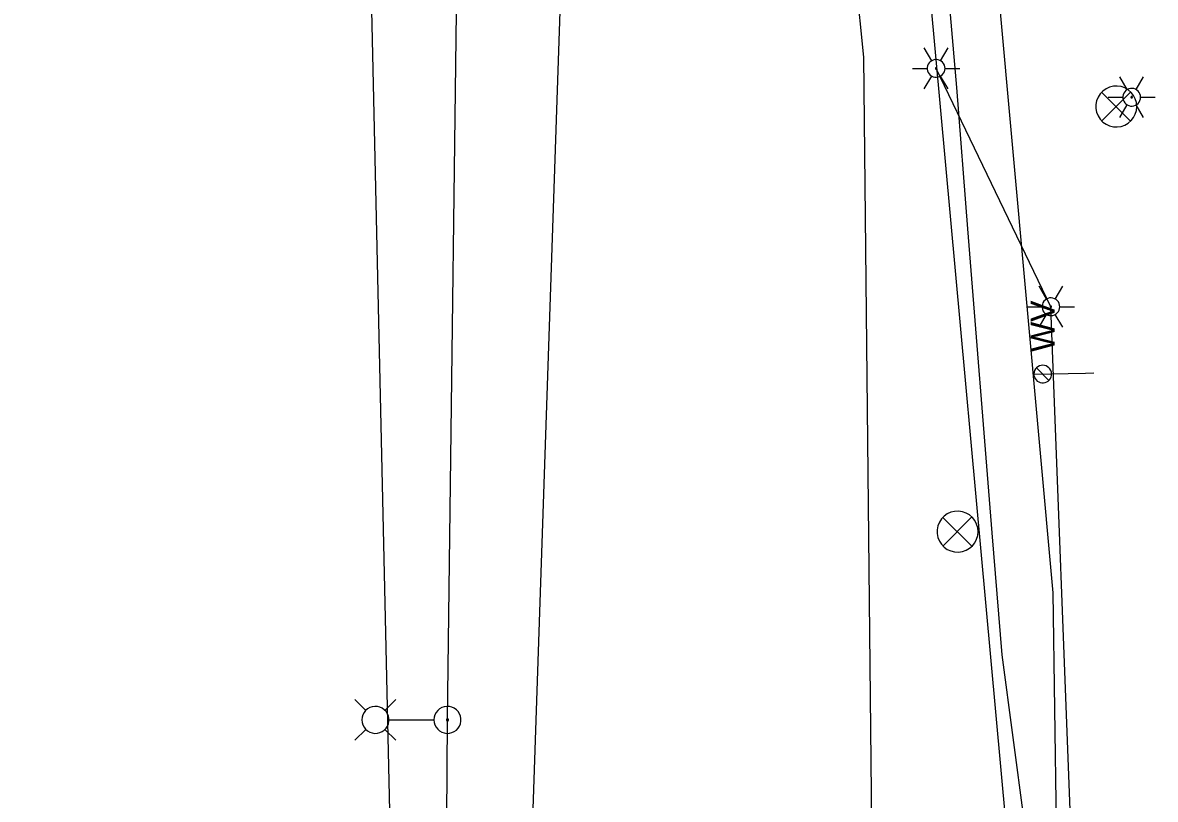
# Model space of a CAD drawing. Extents: x 596028 to 606371, y 330010 to 403088.
# Drawn here: x 604931.9 to 605114.3, y 332771 to 332896.2 of the extents above; entities that cross this region are included whole.
import ezdxf

# ---------------------------------------------------------------- set-up
doc = ezdxf.new("R2010")
doc.units = 0
for name, color, linetype in [('E_LTG', 7, 'Continuous'), ('E_LTG_CID', 7, 'Continuous'), ('E_SIG', 7, 'Continuous'), ('E_SIG_Conduit', 7, 'Continuous'), ('E_UTL_G_UG', 7, 'Continuous'), ('E_UTL_SAN_UG', 7, 'Continuous'), ('E_UTL_SAN_UG_MMSD', 7, 'Continuous'), ('E_UTL_TV', 7, 'Continuous'), ('E_UTL_TV_UG', 7, 'Continuous'), ('E_UTL_W', 7, 'Continuous'), ('E_UTL_W_UG', 7, 'Continuous')]:
    doc.layers.add(name, color=color, linetype=linetype)

msp = doc.modelspace()

# ---------------------------------------------------------------- linework, layer by layer
at = {"layer": 'E_LTG'}
for points in [[(605078.31, 332890.08), (605077.11, 332892.14)], [(605079.73, 332890.08), (605080.93, 332892.14)], [(605080.45, 332888.84), (605080.42, 332889.11), (605080.35, 332889.38), (605080.22, 332889.62), (605080.05, 332889.83), (605079.85, 332890.01), (605079.61, 332890.14), (605079.36, 332890.23), (605079.09, 332890.27), (605078.82, 332890.26), (605078.55, 332890.19), (605078.31, 332890.08), (605078.08, 332889.92), (605077.9, 332889.73), (605077.75, 332889.5), (605077.65, 332889.25), (605077.6, 332888.98), (605077.6, 332888.71), (605077.65, 332888.44), (605077.75, 332888.19), (605077.9, 332887.96), (605078.08, 332887.76), (605078.31, 332887.61), (605078.55, 332887.49), (605078.82, 332887.43), (605079.09, 332887.42), (605079.36, 332887.46), (605079.61, 332887.54), (605079.85, 332887.68), (605080.05, 332887.86), (605080.22, 332888.07), (605080.35, 332888.31), (605080.42, 332888.57), (605080.45, 332888.84)], [(605080.45, 332888.84), (605080.42, 332889.11), (605080.35, 332889.38), (605080.22, 332889.62), (605080.05, 332889.83), (605079.85, 332890.01), (605079.61, 332890.14), (605079.36, 332890.23), (605079.09, 332890.27), (605078.82, 332890.26), (605078.55, 332890.19), (605078.31, 332890.08), (605078.08, 332889.92), (605077.9, 332889.73), (605077.75, 332889.5), (605077.65, 332889.25), (605077.6, 332888.98), (605077.6, 332888.71), (605077.65, 332888.44), (605077.75, 332888.19), (605077.9, 332887.96), (605078.08, 332887.76), (605078.31, 332887.61), (605078.55, 332887.49), (605078.82, 332887.43), (605079.09, 332887.42), (605079.36, 332887.46), (605079.61, 332887.54), (605079.85, 332887.68), (605080.05, 332887.86), (605080.22, 332888.07), (605080.35, 332888.31), (605080.42, 332888.57), (605080.45, 332888.84)], [(605080.45, 332888.84), (605080.42, 332889.11), (605080.35, 332889.38), (605080.22, 332889.62), (605080.05, 332889.83), (605079.85, 332890.01), (605079.61, 332890.14), (605079.36, 332890.23), (605079.09, 332890.27), (605078.82, 332890.26), (605078.55, 332890.19), (605078.31, 332890.08), (605078.08, 332889.92), (605077.9, 332889.73), (605077.75, 332889.5), (605077.65, 332889.25), (605077.6, 332888.98), (605077.6, 332888.71), (605077.65, 332888.44), (605077.75, 332888.19), (605077.9, 332887.96), (605078.08, 332887.76), (605078.31, 332887.61), (605078.55, 332887.49), (605078.82, 332887.43), (605079.09, 332887.42), (605079.36, 332887.46), (605079.61, 332887.54), (605079.85, 332887.68), (605080.05, 332887.86), (605080.22, 332888.07), (605080.35, 332888.31), (605080.42, 332888.57), (605080.45, 332888.84)], [(605075.21, 332888.84), (605077.59, 332888.84)], [(605079.14, 332888.84), (605079.14, 332888.87), (605079.13, 332888.89), (605079.12, 332888.91), (605079.11, 332888.93), (605079.09, 332888.94), (605079.07, 332888.95), (605079.05, 332888.96), (605079.03, 332888.96), (605079, 332888.96), (605078.98, 332888.96), (605078.96, 332888.95), (605078.94, 332888.93), (605078.93, 332888.92), (605078.91, 332888.9), (605078.91, 332888.88), (605078.9, 332888.86), (605078.9, 332888.83), (605078.91, 332888.81), (605078.91, 332888.79), (605078.93, 332888.77), (605078.94, 332888.75), (605078.96, 332888.74), (605078.98, 332888.73), (605079, 332888.73), (605079.03, 332888.73), (605079.05, 332888.73), (605079.07, 332888.74), (605079.09, 332888.75), (605079.11, 332888.76), (605079.12, 332888.78), (605079.13, 332888.8), (605079.14, 332888.82), (605079.14, 332888.84)], [(605080.45, 332888.84), (605082.83, 332888.84)], [(605077.11, 332885.54), (605078.31, 332887.61)], [(605080.93, 332885.54), (605079.73, 332887.61)], [(605109.81, 332885.43), (605108.62, 332887.5)], [(605111.24, 332885.43), (605112.43, 332887.5)], [(605111.95, 332884.2), (605111.93, 332884.47), (605111.85, 332884.73), (605111.73, 332884.97), (605111.56, 332885.18), (605111.35, 332885.36), (605111.12, 332885.5), (605110.86, 332885.58), (605110.59, 332885.62), (605110.32, 332885.61), (605110.06, 332885.55), (605109.81, 332885.43), (605109.59, 332885.28), (605109.4, 332885.08), (605109.25, 332884.85), (605109.15, 332884.6), (605109.1, 332884.33), (605109.1, 332884.06), (605109.15, 332883.79), (605109.25, 332883.54), (605109.4, 332883.31), (605109.59, 332883.12), (605109.81, 332882.96), (605110.06, 332882.85), (605110.32, 332882.78), (605110.59, 332882.77), (605110.86, 332882.81), (605111.12, 332882.9), (605111.35, 332883.03), (605111.56, 332883.21), (605111.73, 332883.42), (605111.85, 332883.66), (605111.93, 332883.93), (605111.95, 332884.2)], [(605111.95, 332884.2), (605111.93, 332884.47), (605111.85, 332884.73), (605111.73, 332884.97), (605111.56, 332885.18), (605111.35, 332885.36), (605111.12, 332885.5), (605110.86, 332885.58), (605110.59, 332885.62), (605110.32, 332885.61), (605110.06, 332885.55), (605109.81, 332885.43), (605109.59, 332885.28), (605109.4, 332885.08), (605109.25, 332884.85), (605109.15, 332884.6), (605109.1, 332884.33), (605109.1, 332884.06), (605109.15, 332883.79), (605109.25, 332883.54), (605109.4, 332883.31), (605109.59, 332883.12), (605109.81, 332882.96), (605110.06, 332882.85), (605110.32, 332882.78), (605110.59, 332882.77), (605110.86, 332882.81), (605111.12, 332882.9), (605111.35, 332883.03), (605111.56, 332883.21), (605111.73, 332883.42), (605111.85, 332883.66), (605111.93, 332883.93), (605111.95, 332884.2)], [(605111.95, 332884.2), (605111.93, 332884.47), (605111.85, 332884.73), (605111.73, 332884.97), (605111.56, 332885.18), (605111.35, 332885.36), (605111.12, 332885.5), (605110.86, 332885.58), (605110.59, 332885.62), (605110.32, 332885.61), (605110.06, 332885.55), (605109.81, 332885.43), (605109.59, 332885.28), (605109.4, 332885.08), (605109.25, 332884.85), (605109.15, 332884.6), (605109.1, 332884.33), (605109.1, 332884.06), (605109.15, 332883.79), (605109.25, 332883.54), (605109.4, 332883.31), (605109.59, 332883.12), (605109.81, 332882.96), (605110.06, 332882.85), (605110.32, 332882.78), (605110.59, 332882.77), (605110.86, 332882.81), (605111.12, 332882.9), (605111.35, 332883.03), (605111.56, 332883.21), (605111.73, 332883.42), (605111.85, 332883.66), (605111.93, 332883.93), (605111.95, 332884.2)], [(605106.71, 332884.2), (605109.1, 332884.2)], [(605108.62, 332880.9), (605109.81, 332882.96)], [(605110.64, 332884.2), (605110.64, 332884.22), (605110.63, 332884.24), (605110.62, 332884.26), (605110.61, 332884.28), (605110.59, 332884.29), (605110.57, 332884.3), (605110.55, 332884.31), (605110.53, 332884.31), (605110.51, 332884.31), (605110.49, 332884.31), (605110.46, 332884.3), (605110.45, 332884.29), (605110.43, 332884.27), (605110.42, 332884.25), (605110.41, 332884.23), (605110.41, 332884.21), (605110.41, 332884.18), (605110.41, 332884.16), (605110.42, 332884.14), (605110.43, 332884.12), (605110.45, 332884.11), (605110.46, 332884.09), (605110.49, 332884.08), (605110.51, 332884.08), (605110.53, 332884.08), (605110.55, 332884.08), (605110.57, 332884.09), (605110.59, 332884.1), (605110.61, 332884.11), (605110.62, 332884.13), (605110.63, 332884.15), (605110.64, 332884.17), (605110.64, 332884.2)], [(605112.43, 332880.9), (605111.24, 332882.96)], [(605111.95, 332884.2), (605114.33, 332884.2)], [(605096.79, 332851.65), (605095.6, 332853.71)], [(605098.22, 332851.65), (605099.41, 332853.71)], [(605098.93, 332850.41), (605098.91, 332850.69), (605098.83, 332850.95), (605098.71, 332851.19), (605098.54, 332851.4), (605098.33, 332851.58), (605098.1, 332851.71), (605097.84, 332851.8), (605097.57, 332851.84), (605097.3, 332851.83), (605097.04, 332851.77), (605096.79, 332851.65), (605096.57, 332851.49), (605096.38, 332851.3), (605096.23, 332851.07), (605096.13, 332850.82), (605096.08, 332850.55), (605096.08, 332850.28), (605096.13, 332850.01), (605096.23, 332849.76), (605096.38, 332849.53), (605096.57, 332849.34), (605096.79, 332849.18), (605097.04, 332849.06), (605097.3, 332849), (605097.57, 332848.99), (605097.84, 332849.03), (605098.1, 332849.12), (605098.33, 332849.25), (605098.54, 332849.43), (605098.71, 332849.64), (605098.83, 332849.88), (605098.91, 332850.14), (605098.93, 332850.41)], [(605098.93, 332850.41), (605098.91, 332850.69), (605098.83, 332850.95), (605098.71, 332851.19), (605098.54, 332851.4), (605098.33, 332851.58), (605098.1, 332851.71), (605097.84, 332851.8), (605097.57, 332851.84), (605097.3, 332851.83), (605097.04, 332851.77), (605096.79, 332851.65), (605096.57, 332851.49), (605096.38, 332851.3), (605096.23, 332851.07), (605096.13, 332850.82), (605096.08, 332850.55), (605096.08, 332850.28), (605096.13, 332850.01), (605096.23, 332849.76), (605096.38, 332849.53), (605096.57, 332849.34), (605096.79, 332849.18), (605097.04, 332849.06), (605097.3, 332849), (605097.57, 332848.99), (605097.84, 332849.03), (605098.1, 332849.12), (605098.33, 332849.25), (605098.54, 332849.43), (605098.71, 332849.64), (605098.83, 332849.88), (605098.91, 332850.14), (605098.93, 332850.41)], [(605098.93, 332850.41), (605098.91, 332850.69), (605098.83, 332850.95), (605098.71, 332851.19), (605098.54, 332851.4), (605098.33, 332851.58), (605098.1, 332851.71), (605097.84, 332851.8), (605097.57, 332851.84), (605097.3, 332851.83), (605097.04, 332851.77), (605096.79, 332851.65), (605096.57, 332851.49), (605096.38, 332851.3), (605096.23, 332851.07), (605096.13, 332850.82), (605096.08, 332850.55), (605096.08, 332850.28), (605096.13, 332850.01), (605096.23, 332849.76), (605096.38, 332849.53), (605096.57, 332849.34), (605096.79, 332849.18), (605097.04, 332849.06), (605097.3, 332849), (605097.57, 332848.99), (605097.84, 332849.03), (605098.1, 332849.12), (605098.33, 332849.25), (605098.54, 332849.43), (605098.71, 332849.64), (605098.83, 332849.88), (605098.91, 332850.14), (605098.93, 332850.41)], [(605093.69, 332850.41), (605096.08, 332850.41)], [(605097.62, 332850.41), (605097.62, 332850.44), (605097.61, 332850.46), (605097.6, 332850.48), (605097.59, 332850.5), (605097.57, 332850.51), (605097.55, 332850.52), (605097.53, 332850.53), (605097.51, 332850.53), (605097.49, 332850.53), (605097.47, 332850.53), (605097.44, 332850.52), (605097.43, 332850.5), (605097.41, 332850.49), (605097.4, 332850.47), (605097.39, 332850.45), (605097.39, 332850.43), (605097.39, 332850.4), (605097.39, 332850.38), (605097.4, 332850.36), (605097.41, 332850.34), (605097.43, 332850.33), (605097.44, 332850.31), (605097.47, 332850.3), (605097.49, 332850.3), (605097.51, 332850.3), (605097.53, 332850.3), (605097.55, 332850.31), (605097.57, 332850.32), (605097.59, 332850.33), (605097.6, 332850.35), (605097.61, 332850.37), (605097.62, 332850.39), (605097.62, 332850.41)], [(605098.93, 332850.41), (605101.31, 332850.41)], [(605095.6, 332847.11), (605096.79, 332849.18)], [(605099.41, 332847.11), (605098.22, 332849.18)], [(604987.16, 332785.33), (604985.39, 332787.11)], [(604990.21, 332785.33), (604991.99, 332787.11)], [(604986.51, 332783.81), (604986.55, 332783.39), (604986.67, 332783), (604986.86, 332782.63), (604987.11, 332782.3), (604987.43, 332782.03), (604987.78, 332781.83), (604988.18, 332781.69), (604988.58, 332781.63), (604989, 332781.65), (604989.4, 332781.75), (604989.78, 332781.92), (604990.11, 332782.16), (604990.4, 332782.46), (604990.62, 332782.81), (604990.78, 332783.19), (604990.85, 332783.6), (604990.85, 332784.01), (604990.78, 332784.42), (604990.62, 332784.8), (604990.4, 332785.15), (604990.11, 332785.45), (604989.78, 332785.69), (604989.4, 332785.86), (604989, 332785.96), (604988.58, 332785.98), (604988.18, 332785.92), (604987.78, 332785.78), (604987.43, 332785.58), (604987.11, 332785.31), (604986.86, 332784.98), (604986.67, 332784.61), (604986.55, 332784.22), (604986.51, 332783.81)], [(604998.12, 332783.81), (604998.16, 332783.39), (604998.27, 332783), (604998.46, 332782.63), (604998.72, 332782.3), (604999.03, 332782.03), (604999.39, 332781.83), (604999.78, 332781.69), (605000.19, 332781.63), (605000.6, 332781.65), (605001, 332781.75), (605001.38, 332781.92), (605001.72, 332782.16), (605002, 332782.46), (605002.23, 332782.81), (605002.38, 332783.19), (605002.46, 332783.6), (605002.46, 332784.01), (605002.38, 332784.42), (605002.23, 332784.8), (605002, 332785.15), (605001.72, 332785.45), (605001.38, 332785.69), (605001, 332785.86), (605000.6, 332785.96), (605000.19, 332785.98), (604999.78, 332785.92), (604999.39, 332785.78), (604999.03, 332785.58), (604998.72, 332785.31), (604998.46, 332784.98), (604998.27, 332784.61), (604998.16, 332784.22), (604998.12, 332783.81)], [(604990.9, 332783.81), (604998.08, 332783.81)], [(605000.13, 332783.81), (605000.13, 332783.77), (605000.14, 332783.74), (605000.15, 332783.72), (605000.17, 332783.69), (605000.2, 332783.67), (605000.22, 332783.65), (605000.25, 332783.64), (605000.28, 332783.64), (605000.32, 332783.64), (605000.35, 332783.65), (605000.38, 332783.66), (605000.4, 332783.68), (605000.42, 332783.7), (605000.44, 332783.73), (605000.45, 332783.76), (605000.46, 332783.79), (605000.46, 332783.82), (605000.45, 332783.85), (605000.44, 332783.88), (605000.42, 332783.91), (605000.4, 332783.93), (605000.38, 332783.95), (605000.35, 332783.96), (605000.32, 332783.97), (605000.28, 332783.97), (605000.25, 332783.97), (605000.22, 332783.96), (605000.2, 332783.94), (605000.17, 332783.92), (605000.15, 332783.9), (605000.14, 332783.87), (605000.13, 332783.84), (605000.13, 332783.81)], [(604987.16, 332782.28), (604985.39, 332780.51)], [(604990.21, 332782.28), (604991.99, 332780.51)]]:
    msp.add_lwpolyline(points, dxfattribs=at)
at = {"layer": 'E_LTG_CID'}
for points in [[(604931.85, 331581.07), (604937.27, 331603.67), (604947.8, 331650.94), (604952, 331678.28), (604955.83, 331701.76), (604989.48, 331966.47), (604996.27, 332242.26), (604998.49, 332512.59), (605000.29, 332783.81), (605002.15, 332931.75), (605000.64, 332964.83), (605000.69, 332966.2), (605002.17, 333011.44), (605003.78, 333073.37), (605005.15, 333128.46), (605004.43, 333142.5)], [(605100.78, 332765.04), (605097.5, 332850.41), (605079.02, 332888.84)]]:
    msp.add_lwpolyline(points, dxfattribs=at)
at = {"layer": 'E_SIG'}
for points in [[(605111.35, 332882.69), (605111.29, 332883.32), (605111.11, 332883.92), (605110.83, 332884.48), (605110.44, 332884.97), (605109.96, 332885.38), (605109.42, 332885.7), (605108.83, 332885.9), (605108.21, 332885.99), (605107.58, 332885.96), (605106.97, 332885.81), (605106.4, 332885.55), (605105.89, 332885.19), (605105.46, 332884.73), (605105.12, 332884.21), (605104.88, 332883.62), (605104.76, 332883.01), (605104.76, 332882.38), (605104.88, 332881.76), (605105.12, 332881.18), (605105.46, 332880.65), (605105.89, 332880.2), (605106.4, 332879.84), (605106.97, 332879.58), (605107.58, 332879.43), (605108.21, 332879.4), (605108.83, 332879.49), (605109.42, 332879.69), (605109.96, 332880.01), (605110.44, 332880.42), (605110.83, 332880.91), (605111.11, 332881.47), (605111.29, 332882.07), (605111.35, 332882.69)], [(605110.31, 332885.03), (605105.7, 332880.37)], [(605105.7, 332884.98), (605110.35, 332880.33)]]:
    msp.add_lwpolyline(points, dxfattribs=at)
at = {"layer": 'E_SIG_Conduit'}
msp.add_lwpolyline([(605013.44, 332750.37), (605018.8, 332909.2), (605014.77, 333003.78)], dxfattribs=at)
at = {"layer": 'E_UTL_G_UG'}
for points in [[(605067.35, 332890.68), (605061.21, 332951.97), (605055.05, 333004.59), (605053.86, 333028.21), (605052.5, 333057.99), (605051.57, 333081.36), (605049.66, 333125.99), (605049.8, 333176.37), (605050.05, 333219.56), (605051.36, 333273.68), (605051.84, 333298.93), (605052.97, 333353.42), (605053.54, 333377.39), (605054.31, 333435.25), (605055.56, 333475.58), (605057.16, 333564.52), (605058.44, 333615), (605058.65, 333665.55), (605058.49, 333700.45), (605060.44, 333765.47), (605057.13, 333874.76), (605051.05, 333995.08)], [(605069.91, 332651.64), (605069.52, 332684.31), (605067.35, 332890.68)], [(605090.74, 332777.32), (605090.74, 332777.32)]]:
    msp.add_lwpolyline(points, dxfattribs=at)
at = {"layer": 'E_UTL_SAN_UG'}
msp.add_line((605095.5, 332710.46), (605061.78, 333078.09), dxfattribs=at)
at = {"layer": 'E_UTL_SAN_UG_MMSD'}
msp.add_lwpolyline([(604992.09, 332721.29), (604978.83, 333311.92)], dxfattribs=at)
at = {"layer": 'E_UTL_TV'}
for points in [[(605085.77, 332814.16), (605085.71, 332814.78), (605085.54, 332815.38), (605085.25, 332815.94), (605084.86, 332816.43), (605084.39, 332816.84), (605083.84, 332817.16), (605083.25, 332817.36), (605082.63, 332817.45), (605082, 332817.42), (605081.39, 332817.27), (605080.82, 332817.01), (605080.31, 332816.65), (605079.88, 332816.2), (605079.54, 332815.67), (605079.31, 332815.09), (605079.19, 332814.47), (605079.19, 332813.84), (605079.31, 332813.23), (605079.54, 332812.64), (605079.88, 332812.12), (605080.31, 332811.66), (605080.82, 332811.3), (605081.39, 332811.04), (605082, 332810.89), (605082.63, 332810.86), (605083.25, 332810.95), (605083.84, 332811.15), (605084.39, 332811.47), (605084.86, 332811.88), (605085.25, 332812.37), (605085.54, 332812.93), (605085.71, 332813.53), (605085.77, 332814.16)], [(605084.73, 332816.49), (605080.12, 332811.83)], [(605080.12, 332816.44), (605084.78, 332811.79)]]:
    msp.add_lwpolyline(points, dxfattribs=at)
at = {"layer": 'E_UTL_TV_UG'}
msp.add_lwpolyline([(605094.66, 332749.57), (605093.19, 332767.66), (605089.64, 332794.29), (605088.03, 332813.98), (605084.1, 332862.98), (605082.36, 332885.78), (605078.4, 332931.64), (605073.44, 332982.37), (605071.45, 333013.37), (605067.62, 333058.93), (605065.49, 333085.16), (605061.42, 333132.77), (605058.07, 333175.2), (605056.52, 333223.42), (605057.28, 333240.58), (605057.66, 333247.69), (605057.53, 333257.64), (605054.7, 333270.55), (605051.63, 333282.99), (605048.15, 333292.97), (605046.32, 333306.44), (605046.78, 333343.6), (605047.66, 333380.14), (605052.04, 333566.05)], dxfattribs=at)
at = {"layer": 'E_UTL_W'}
for points in [[(605096.19, 332840.98), (605095.92, 332840.95), (605095.66, 332840.88), (605095.42, 332840.75), (605095.21, 332840.59), (605095.03, 332840.38), (605094.89, 332840.15), (605094.8, 332839.89), (605094.77, 332839.62), (605094.78, 332839.35), (605094.84, 332839.09), (605094.95, 332838.84), (605095.11, 332838.62), (605095.31, 332838.43), (605095.54, 332838.29), (605095.79, 332838.19), (605096.05, 332838.13), (605096.33, 332838.13), (605096.59, 332838.19), (605096.84, 332838.29), (605097.07, 332838.43), (605097.27, 332838.62), (605097.42, 332838.84), (605097.54, 332839.09), (605097.6, 332839.35), (605097.61, 332839.62), (605097.58, 332839.89), (605097.49, 332840.15), (605097.35, 332840.38), (605097.17, 332840.59), (605096.96, 332840.75), (605096.72, 332840.88), (605096.46, 332840.95), (605096.19, 332840.98)], [(605097.2, 332838.55), (605095.18, 332840.56)]]:
    msp.add_lwpolyline(points, dxfattribs=at)
at = {"layer": 'E_UTL_W_UG'}
for p, q in [((605097.89, 332804.29), (605065.96, 333156.25)), ((605098.99, 332724.07), (605097.89, 332804.29))]:
    msp.add_line(p, q, dxfattribs=at)
msp.add_lwpolyline([(605094.69, 332839.52), (605103.1, 332839.72), (605104.42, 332839.75)], dxfattribs=at)

# ---------------------------------------------------------------- texts
at = {"layer": 'E_UTL_W'}
msp.add_text('WV', height=3.85, rotation=90, dxfattribs=at).set_placement((605098.11, 332843.12))

doc.saveas('drawing.dxf')
